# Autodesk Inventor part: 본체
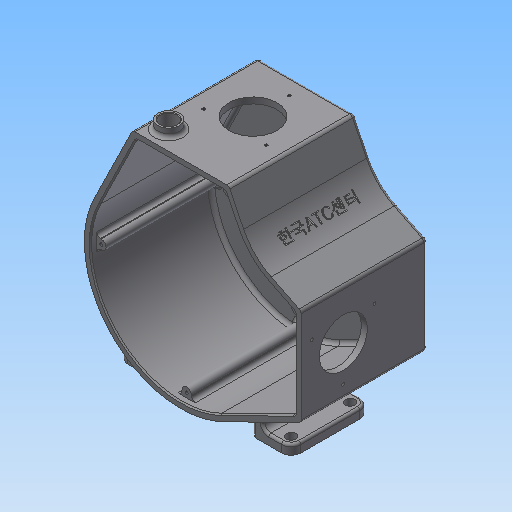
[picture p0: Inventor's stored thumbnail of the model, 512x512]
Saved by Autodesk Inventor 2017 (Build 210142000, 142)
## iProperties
Created: 2017-05
Part Number: 본체
Material: 일반
Document SubType Name: Modeling
Designer: mduedu
Density: 1 g/cm^3
Appearance: 기본값
Author: mduedu
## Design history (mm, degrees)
sketch "스케치1"
  geometry: L1 (-71.801, 35.28)-(-40, 100); L2 (-40, 100)-(40, 100); L3 (40, 100)-(59.768, 59.768); L4 (59.768, 59.768)-(100, 40); L5 (100, 40)-(100, -40); L6 (100, -40)-(35.28, -71.801); A1 r 80 centre (0, 0) between (-71.801, 35.28) and (35.28, -71.801); 3 further points
  constraints: 12 end point, 4 tangent, 2 midpoint, 2 point on circle, 1 centre point, 1 coincident, 1 horizontal, 1 horizontal alignment, 1 perpendicular, 1 vertical alignment
  dimensions: "d0" = 160 diameter of A1; "d2" = 100 distance from line of L2 point (0, 0); "d3" = 100 distance from line of L5 point (0, 0); "d4" = 80 distance of L1.end L2.end; "d5" = 80 distance of L4.end L5.end
extrude "돌출1" new body sketch "스케치1" distance "d6" = 5; taper "d7" = 0 deg
fillet "모깎기1" dims "d8" = 50
sketch "스케치2"
  geometry: C1 r 22 at (0, 0); 1 further point
  constraints: 1 centre point, 1 coincident
  dimensions: "d9" = 44 diameter of C1
extrude "돌출2" join sketch "스케치2" distance "d10" = 22.5; taper "d11" = 0 deg
sketch "스케치3"
  geometry: C1 r 18.5 at (0, 0); 1 further point
  constraints: 1 centre point, 1 coincident
  dimensions: "d12" = 37 diameter of C1
extrude "돌출3" cut sketch "스케치3" distance "d13" = 9; taper "d14" = 0 deg
fillet "모깎기2" dims "d15" = 3
sketch "스케치4"
  geometry: L1 (35.28, -71.801)-(100, -40) reference; L2 (100, -40)-(100, 40) reference; L3 (100, 40)-(75.073, 52.248) reference; L4 (52.248, 75.073)-(40, 100) reference; L5 (40, 100)-(-40, 100) reference; L6 (-40, 100)-(-71.801, 35.28) reference; L7 (-36.886, 95)-(36.886, 95); L8 (36.886, 95)-(47.76, 72.868); L9 (72.868, 47.76)-(95, 36.886); L10 (95, 36.886)-(95, -36.886); L11 (95, -36.886)-(33.075, -67.313); L12 (-67.313, 33.075)-(-36.886, 95); C1 r 25 at (0, 0) reference; A1 r 50 centre (97.123, 97.123) between (52.248, 75.073) and (75.073, 52.248) reference; A2 r 80 centre (0, 0) between (-71.801, 35.28) and (35.28, -71.801) reference; A3 r 55 centre (97.123, 97.123) between (47.76, 72.868) and (72.868, 47.76); A4 r 75 centre (0, 0) between (-67.313, 33.075) and (33.075, -67.313); 1 further point
  constraints: 12 end point, 4 point on circle, 2 centre point, 7 other
  dimensions: "d16" = 5 distance between parallel lines of L7 L5
extrude "돌출4" join sketch "스케치4" distance "d17" = 100; taper "d18" = 0 deg
sketch "스케치5"
  geometry: L1 (80, 0)-(0, 0) reference; C1 r 20 at (40, -45); 2 further points
  constraints: 1 centre point, 1 midpoint, 1 vertical alignment
  dimensions: "d19" = 40 diameter of C1; "d21" = 45 distance from line of C1.centre L1
extrude "돌출5" cut sketch "스케치5" stored distance "d22" = 100; taper "d23" = 0 deg
sketch "스케치6"
  geometry: L1 (0, 0)-(0, -105) reference; L2 (80, -105)-(0, -105) reference; C1 r 9 at (14, -89); 1 further point
  constraints: 1 centre point
  dimensions: "d24" = 18 diameter of C1; "d26" = 14 distance from line of C1.centre L1; "d27" = 16 distance from line of C1.centre L2
extrude "돌출6" join sketch "스케치6" distance "d28" = 7; taper "d29" = 0 deg
hole "구멍1" diameter "d32" = 14; stored, may be unused: countersink angle "d36" = 90 deg, drill point angle "d38" = 118 deg; dims "d33" = 6, "d34" = 4, "d35" = 2, "d37" = 8, "d39" = 10, "d40" = 10
sketch "스케치7"
  geometry: L1 (-105, 0)-(-105, 80) reference; L2 (0, 0)-(0, 80) reference; C1 r 20 at (-70, 40); 2 further points
  constraints: 1 centre point, 1 horizontal alignment, 1 midpoint
  dimensions: "d41" = 40 diameter of C1; "d42" = 35 distance from line of C1.centre L1
extrude "돌출7" cut sketch "스케치7" stored distance "d43" = 7; taper "d44" = 0 deg
node "작업 평면1"
sketch "스케치8"
  geometry: L1 (47.76, 72.868)-(36.886, 95) reference; L2 (36.886, 95)-(-36.886, 95) reference; L3 (-36.886, 95)-(-67.313, 33.075) reference; L4 (33.075, -67.313)-(95, -36.886) reference; L5 (95, -36.886)-(95, 36.886) reference; L6 (95, 36.886)-(72.868, 47.76) reference; L7 (95, 36.886)-(95, -36.886) reference; L8 (-36.886, 95)-(36.886, 95) reference; L9 (36.886, 95)-(47.76, 72.868) reference; L10 (-71, 4)-(-74.893, 4); L11 (-71, -4)-(-74.893, -4); L12 (-4, -71)-(-4, -74.893); L13 (4, -71)-(4, -74.893); L14 (30.394, 91)-(30.394, 95); L15 (34.394, 87)-(40.817, 87); L16 (30.394, 95)-(36.886, 95); L17 (36.886, 95)-(37.984, 92.764); L18 (91, 30.394)-(95, 30.394); L19 (87, 34.394)-(87, 40.817); L20 (87, 40.817)-(95, 36.886); L21 (95, 36.886)-(95, 30.394); C1 r 25 at (0, 0) reference; A1 r 75 centre (0, 0) between (-67.313, 33.075) and (33.075, -67.313) reference; A2 r 55 centre (97.123, 97.123) between (47.76, 72.868) and (72.868, 47.76) reference; A3 r 4 centre (-71, 0) between (-71, 4) and (-71, -4); A4 r 4 centre (0, -71) between (-4, -71) and (4, -71); A5 r 4 centre (34.394, 91) between (30.394, 91) and (34.394, 87); A6 r 75 centre (0, 0) between (-67.313, 33.075) and (33.075, -67.313) reference; A7 r 4 centre (91, 34.394) between (91, 30.394) and (87, 34.394); 1 further point
  constraints: 24 end point, 17 point on circle, 14 tangent, 5 point on line, 4 centre point, 3 equal radius, 3 perpendicular, 3 vertical, 2 collinear, 2 horizontal, 1 horizontal alignment, 1 parallel, 1 vertical alignment
  dimensions: "d46" = 8 diameter of A3
extrude "돌출8" join sketch "스케치8" stored distance "d49" = 7; taper "d50" = 0 deg
node "작업 평면2"
sketch "스케치9"
  geometry: L1 (71.801, 0)-(71.801, 105) reference; L2 (71.801, 0)-(-35.28, 0) reference; L3 (-35.28, 0)-(-35.28, 105) reference; L4 (71.801, 105)-(-35.28, 105) reference; L5 (40, 0)-(40, 105) reference; L6 (71.801, 52.5)-(-35.28, 52.5); L7 (71.801, 20)-(40, 20); L8 (40, 20)-(40, 85); L9 (40, 85)-(71.801, 85); L10 (71.801, 85)-(71.801, 20); 1 further point
  constraints: 10 end point, 2 midpoint, 2 parallel, 2 point on line, 1 horizontal, 1 perpendicular, 1 other
  dimensions: "d52" = 20 distance between parallel lines of L7 L2
extrude "돌출9" join sketch "스케치9" distance "d53" = 8; taper "d54" = 0 deg
fillet "모깎기3" dims "d55" = 8
sketch "스케치10"
  geometry: C1 r 4 at (-63.801, -28); C2 r 4 at (-63.801, -77); A1 r 8 centre (-63.801, -28) between (-63.801, -20) and (-71.801, -28) reference; A2 r 8 centre (-63.801, -77) between (-71.801, -77) and (-63.801, -85) reference; 1 further point
  constraints: 2 centre point, 2 coincident, 1 equal radius
  dimensions: "d56" = 8 diameter of C1
extrude "돌출10" cut sketch "스케치10" stored distance "d57" = 50.5; taper "d58" = 0 deg
sketch "스케치11"
  geometry: L1 (-63.801, -20)-(-40, -20) reference; L2 (-40, -20)-(-40, -85) reference; L3 (-40, -85)-(-63.801, -85) reference; L4 (-71.801, -77)-(-71.801, -28) reference; L5 (71.801, -77)-(71.801, -28) reference; L6 (40, -85)-(63.801, -85) reference; L7 (40, -20)-(40, -85) reference; L8 (63.801, -20)-(40, -20) reference; L9 (-40, -85)-(-48, -85); L10 (-48, -85)-(-48, -20); L11 (-48, -20)-(-40, -20); L12 (-40, -20)-(-40, -85); L13 (40, -85)-(48, -85); L14 (48, -85)-(48, -20); L15 (48, -20)-(40, -20); L16 (40, -20)-(40, -85); C1 r 4 at (-63.801, -28) reference; C2 r 4 at (-63.801, -77) reference; C3 r 4 at (63.801, -28) reference; C4 r 4 at (63.801, -77) reference; A1 r 8 centre (-63.801, -28) between (-63.801, -20) and (-71.801, -28) reference; A2 r 8 centre (-63.801, -77) between (-71.801, -77) and (-63.801, -85) reference; A3 r 8 centre (63.801, -28) between (71.801, -28) and (63.801, -20) reference; A4 r 8 centre (63.801, -77) between (63.801, -85) and (71.801, -77) reference; 1 further point
  constraints: 16 end point, 4 parallel, 2 horizontal, 2 perpendicular, 2 point on line
  dimensions: "d59" = 8 distance of L10.end L11.end; "d61" = 8 distance of L14.end L15.end
extrude "돌출11" join sketch "스케치11" stored distance "d62" = 5; taper "d63" = 0 deg
fillet "모깎기4" dims "d64" = 5
fillet "모깎기5" dims "d65" = 2
fillet "모깎기6" dims "d66" = 2
fillet "모깎기8" dims "d68" = 2
fillet "모깎기9" dims "d70" = 3, "d101" = 1
fillet "모깎기10" dims "d71" = 3
fillet "모깎기11" dims "d72" = 3
fillet "모깎기12" dims "d73" = 3
fillet "모깎기13" dims "d76" = 3
chamfer "모따기1" distance "d77" = 0.5; stored, may be unused: second distance "d78" = 2, angle "d79" = 45 deg
chamfer "모따기2" distance "d87" = 1; stored, may be unused: second distance "d88" = 2, angle "d89" = 45 deg
chamfer "모따기3" distance "d90" = 1; stored, may be unused: second distance "d91" = 2, angle "d92" = 45 deg
sketch "스케치14"
  geometry: 3 further points
  constraints: 3 other
hole "구멍2" sketch "스케치14" at (-55.375, -40), (-3.414, -40), (-29.394, -85) diameter "d93" = 2.459; stored, may be unused: countersink angle "d97" = 90 deg, drill point angle "d99" = 0 deg; dims "d94" = 6, "d95" = 4, "d96" = 2, "d98" = 8
sketch "스케치15"
  geometry: 3 further points
  constraints: 3 other
hole "구멍4" sketch "스케치15" at (-55.981, -14.394), (-4.019, -14.394), (-30, -59.394) diameter "d102" = 2.459; stored, may be unused: countersink angle "d106" = 90 deg, drill point angle "d108" = 0 deg; dims "d103" = 6, "d104" = 4, "d105" = 2, "d107" = 8
sketch "스케치16"
  geometry: 4 further points
  constraints: 4 other
hole "구멍6" sketch "스케치16" at (0, -71), (91, 34.394), (34.394, 91), (-71, 0) diameter "d109" = 2.459; stored, may be unused: countersink angle "d113" = 90 deg, drill point angle "d115" = 120 deg; dims "d110" = 8.5, "d111" = 4, "d112" = 2, "d114" = 10
node "작업 평면4"
sketch "스케치17"
  geometry: 2 further points
  constraints: 1 horizontal alignment, 1 other
  dimensions: "d116" = 52.5 distance of point (0, 16.14) point (52.5, 16.14)
feature "엠보싱2" sketch "스케치17" dims "d117" = 0.5, "d118" = 0
node "솔리드1"
mirror "대칭1"
node "투영된 루프1"
node "투영된 루프2"
node "투영된 루프3"
node "투영된 루프4"
node "투영된 루프5"
other parameters: "d45" = 95
